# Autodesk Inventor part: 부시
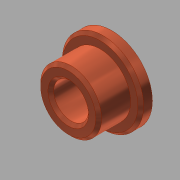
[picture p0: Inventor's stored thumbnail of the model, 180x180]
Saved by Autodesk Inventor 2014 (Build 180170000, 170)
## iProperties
Created: 2016-02
Part Number: 부시
Material: 강철, 연강
Document SubType Name: Modeling
Designer: test
Density: 7.86 g/cm^3
Appearance: 금속 1400F 열
Mass: 35.2265 g
Surface Area: 25.348 cm^2
Volume: 4.48174 cm^3
Author: test
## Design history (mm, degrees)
sketch "스케치1"
  geometry: C1 r 14 at (0, 0); C2 r 10.5 at (0, 0); 1 further point
  constraints: 2 centre point, 2 coincident
  dimensions: "d0" = 28 diameter of C1; "d1" = 21 diameter of C2
extrude "돌출1" new body sketch "스케치1" distance "d2" = 4; taper "d3" = 0 deg
extrude "돌출2" join sketch "스케치1" distance "d4" = 11; taper "d5" = 0 deg
hole "구멍1" diameter "d8" = 12; stored, may be unused: countersink angle "d12" = 90 deg, drill point angle "d14" = 118 deg; dims "d6" = 10, "d7" = 10, "d9" = 6, "d10" = 4, "d11" = 2, "d13" = 8
chamfer "모따기1" distance "d15" = 1; stored, may be unused: second distance "d16" = 2, angle "d17" = 45 deg
chamfer "모따기2" distance "d18" = 1; stored, may be unused: second distance "d19" = 2, angle "d20" = 45 deg
node "솔리드1"
